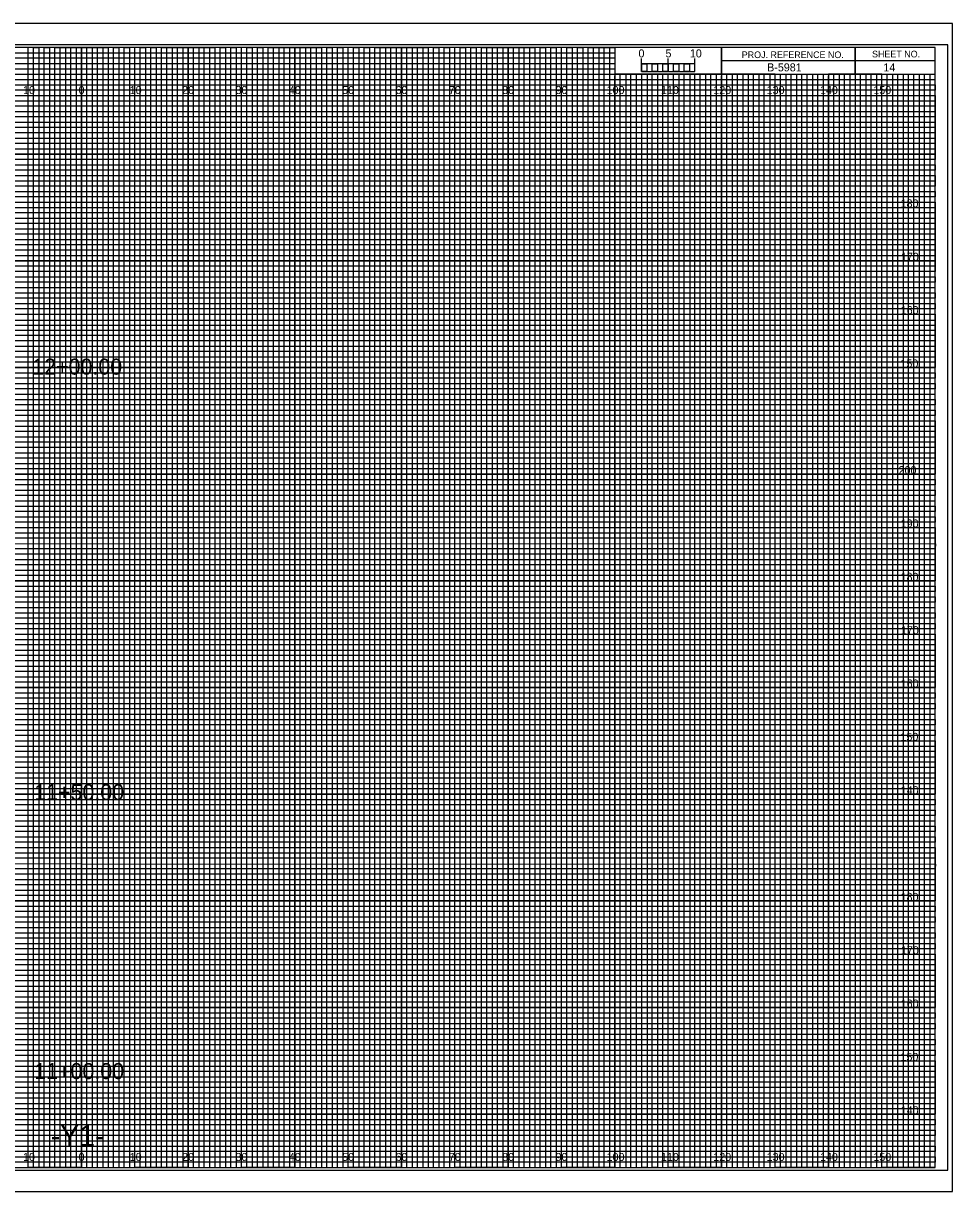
# Model space of a CAD drawing. Extents: x -13 to 323, y -5 to 434.
# Drawn here: x 149.1 to 323.3, y -4.5 to 214.5 of the extents above; entities that cross this region are included whole.
import ezdxf

# ---------------------------------------------------------------- set-up
doc = ezdxf.new("R2010")
doc.units = 0
for name, color, linetype in [('Exist Cross Section Cell', 7, 'Continuous'), ('Exist XS Center Line Elevation Label', 7, 'Continuous'), ('Exist XS Ground Line', 7, 'Continuous'), ('Prop CMT Concrete Structures', 7, 'Continuous'), ('Prop CMT Guardrail Graphics', 7, 'Continuous'), ('Prop CMT Pvmt Course 1', 7, 'Continuous'), ('Prop CMT Pvmt Course 2', 7, 'Continuous'), ('Prop CMT Pvmt Course 3', 7, 'Continuous'), ('Prop CMT Pvmt Surface', 7, 'Continuous'), ('Prop CMT Shld Paved Course 1', 7, 'Continuous'), ('Prop CMT Shld Paved Course 2', 7, 'Continuous'), ('Prop CMT Shld Paved Course 3', 7, 'Continuous'), ('Prop CMT Subgrade Earthwork', 7, 'Continuous'), ('Prop XS Ditch Standard Text', 7, 'Continuous'), ('Prop XS SE Text', 7, 'Continuous'), ('Prop XS Side Slope Text', 7, 'Continuous'), ('Scratch_Level_0', 7, 'Continuous')]:
    doc.layers.add(name, color=color, linetype=linetype)

msp = doc.modelspace()

# ---------------------------------------------------------------- linework, layer by layer
at = {"layer": 'Exist XS Center Line Elevation Label'}
for points in [[(145, 0), (155, 0), (155, 210), (165, 210), (165, 0), (175, 0), (175, 210), (185, 210), (185, 0), (195, 0), (195, 210), (205, 210), (205, 0), (215, 0), (215, 210), (225, 210), (225, 0), (235, 0), (235, 210), (245, 210), (245, 0), (255, 0), (255, 210), (259.93, 210), (260, 210), (260, 205), (264.99, 205), (264.99, 0), (275, 0), (275, 205), (285, 205), (285, 0), (295, 0), (295, 205), (305, 205), (305, 0), (315, 0), (315, 205)], [(0, 205), (275, 205)], [(0, 185), (320, 185), (320, 195), (0, 195)], [(0, 165), (320, 165), (320, 175), (0, 175)], [(0, 145), (320, 145), (320, 155), (0, 155)], [(0, 125), (320, 125), (320, 135), (0, 135)], [(0, 105), (320, 105), (320, 115), (0, 115)], [(0, 85), (320, 85), (320, 95), (0, 95)], [(0, 65), (320, 65), (320, 75), (0, 75)], [(0, 45), (320, 45), (320, 55), (0, 55)], [(0, 25), (320, 25), (320, 35), (0, 35)], [(0, 5), (320, 5), (320, 15), (0, 15)]]:
    msp.add_lwpolyline(points, dxfattribs=at)
at = {"layer": 'Exist XS Ground Line'}
for p, q in [((150, 210), (140, 210)), ((150, 0), (150, 210)), ((170, 210), (160, 210)), ((160, 210), (160, 0)), ((170, 0), (170, 210)), ((190, 210), (180, 210)), ((180, 210), (180, 0)), ((190, 0), (190, 210)), ((210, 210), (200, 210)), ((200, 210), (200, 0)), ((210, 0), (210, 210)), ((230, 210), (220, 210)), ((220, 210), (220, 0)), ((230, 0), (230, 210)), ((250, 210), (240, 210)), ((240, 210), (240, 0)), ((250, 0), (250, 210)), ((260, 210), (260, 0)), ((270, 0), (270, 205)), ((290, 205), (280, 205)), ((280, 205), (280, 0)), ((290, 0), (290, 205)), ((310, 205), (300, 205)), ((300, 205), (300, 0)), ((310, 0), (310, 205)), ((160, 0), (150, 0)), ((180, 0), (170, 0)), ((200, 0), (190, 0)), ((220, 0), (210, 0)), ((240, 0), (230, 0)), ((260, 0), (250, 0)), ((280, 0), (270, 0)), ((300, 0), (290, 0)), ((320, 0), (310, 0)), ((320, 0), (320, 0))]:
    msp.add_line(p, q, dxfattribs=at)
for points in [[(0, 200), (320, 200), (320, 190), (0, 190)], [(0, 180), (320, 180), (320, 170), (0, 170)], [(0, 160), (320, 160), (320, 150), (0, 150)], [(0, 140), (320, 140), (320, 130), (0, 130)], [(0, 120), (320, 120), (320, 110), (0, 110)], [(0, 100), (320, 100), (320, 90), (0, 90)], [(0, 80), (320, 80), (320, 70), (0, 70)], [(0, 60), (320, 60), (320, 50), (0, 50)], [(0, 40), (320, 40), (320, 30), (0, 30)], [(0, 20), (320, 20), (320, 10), (0, 10)]]:
    msp.add_lwpolyline(points, dxfattribs=at)
at = {"layer": 'Prop CMT Pvmt Course 1'}
for p, q in [((323.3, 214.5), (-13.4, 214.5)), ((-13.4, -4.5), (323.3, -4.5))]:
    msp.add_line(p, q, dxfattribs=at)
at = {"layer": 'Prop CMT Pvmt Course 2'}
msp.add_lwpolyline([(-13.4, -4.5), (323.3, -4.5), (323.3, 214.5), (-13.4, 214.5)], close=True, dxfattribs=at)
at = {"layer": 'Prop CMT Pvmt Course 3'}
msp.add_lwpolyline([(-10.8, -0.5), (322.4, -0.5), (322.4, 210.5), (-10.8, 210.5)], close=True, dxfattribs=at)
at = {"layer": 'Prop CMT Shld Paved Course 1'}
for p, q in [((305, 210), (305, 205)), ((305, 205), (305, 210)), ((280, 207.5), (280, 205)), ((320, 207.49), (280, 207.49)), ((280, 205), (320, 205))]:
    msp.add_line(p, q, dxfattribs=at)
for points in [[(320, 210), (0, 210), (0, 0), (320, 0)], [(280, 210), (260, 210), (260, 205.03), (280, 205.03)], [(320, 210), (280, 210), (280, 205), (320, 205)]]:
    msp.add_lwpolyline(points, close=True, dxfattribs=at)
at = {"layer": 'Prop CMT Shld Paved Course 2'}
for p, q in [((267, 205), (266.01, 205)), ((266.01, 205), (266.01, 0)), ((267, 0), (267, 205)), ((269, 205), (268, 205)), ((268, 205), (268, 0)), ((269, 0), (269, 205)), ((266.01, 0), (265, 0)), ((268, 0), (267, 0))]:
    msp.add_line(p, q, dxfattribs=at)
for points in [[(150, 0), (151, 0), (151, 210), (152, 210), (152, 0)], [(152, 0), (153, 0), (153, 210), (154, 210), (154, 0)], [(155, 0), (156, 0), (156, 210), (157, 210), (157, 0)], [(157, 0), (158, 0), (158, 210), (159, 210), (159, 0)], [(160, 0), (161, 0), (161, 210), (162, 210), (162, 0)], [(162, 0), (163, 0), (163, 210), (164, 210), (164, 0)], [(165, 0), (166, 0), (166, 210), (167, 210), (167, 0)], [(167, 0), (168, 0), (168, 210), (169, 210), (169, 0)], [(170, 0), (171, 0), (171, 210), (172, 210), (172, 0)], [(172, 0), (173, 0), (173, 210), (174, 210), (174, 0)], [(175, 0), (176, 0), (176, 210), (177, 210), (177, 0)], [(177, 0), (178, 0), (178, 210), (179, 210), (179, 0)], [(180, 0), (181, 0), (181, 210), (182, 210), (182, 0)], [(182, 0), (183, 0), (183, 210), (184, 210), (184, 0)], [(185, 0), (186, 0), (186, 210), (187, 210), (187, 0)], [(187, 0), (188, 0), (188, 210), (189, 210), (189, 0)], [(190, 0), (191, 0), (191, 210), (192, 210), (192, 0)], [(192, 0), (193, 0), (193, 210), (194, 210), (194, 0)], [(195, 0), (196, 0), (196, 210), (197, 210), (197, 0)], [(197, 0), (198, 0), (198, 210), (199, 210), (199, 0)], [(200, 0), (201, 0), (201, 210), (202, 210), (202, 0)], [(202, 0), (203, 0), (203, 210), (204, 210), (204, 0)], [(205, 0), (206, 0), (206, 210), (207, 210), (207, 0)], [(207, 0), (208, 0), (208, 210), (209, 210), (209, 0)], [(210, 0), (211, 0), (211, 210), (212, 210), (212, 0)], [(212, 0), (213, 0), (213, 210), (214, 210), (214, 0)], [(215, 0), (216, 0), (216, 210), (217, 210), (217, 0)], [(217, 0), (218, 0), (218, 210), (219, 210), (219, 0)], [(220, 0), (221, 0), (221, 210), (222, 210), (222, 0)], [(222, 0), (223, 0), (223, 210), (224, 210), (224, 0)], [(225, 0), (226, 0), (226, 210), (227, 210), (227, 0)], [(227, 0), (228, 0), (228, 210), (229, 210), (229, 0)], [(230, 0), (231, 0), (231, 210), (232, 210), (232, 0)], [(232, 0), (233, 0), (233, 210), (234, 210), (234, 0)], [(235, 0), (236, 0), (236, 210), (237, 210), (237, 0)], [(237, 0), (238, 0), (238, 210), (239, 210), (239, 0)], [(240, 0), (241, 0), (241, 210), (242, 210), (242, 0)], [(242, 0), (243, 0), (243, 210), (244, 210), (244, 0)], [(245, 0), (246, 0), (246, 210), (247, 210), (247, 0)], [(247, 0), (248, 0), (248, 210), (249, 210), (249, 0)], [(250, 0), (251, 0), (251, 210), (252, 210), (252, 0)], [(252, 0), (253, 0), (253, 210), (254, 210), (254, 0)], [(255, 0), (256, 0), (256, 210), (257, 210), (257, 0)], [(257, 0), (258, 0), (258, 210), (259, 210), (259, 0)], [(260, 0), (261, 0), (261, 205), (262.02, 205), (262.02, 0)], [(262, 0), (263, 0), (263, 205), (263.99, 205), (263.99, 0)], [(270, 0), (270.98, 0), (270.98, 205), (272, 205), (272, 0)], [(272, 0), (273, 0), (273, 205), (274.05, 205), (274.05, 0)], [(275, 0), (276, 0), (276, 205), (277, 205), (277, 0)], [(277, 0), (278, 0), (278, 205), (279, 205), (279, 0)], [(280, 0), (281, 0), (281, 205), (282, 205), (282, 0)], [(282, 0), (283, 0), (283, 205), (284, 205), (284, 0)], [(285, 0), (286, 0), (286, 205), (287, 205), (287, 0)], [(287, 0), (288, 0), (288, 205), (289, 205), (289, 0)], [(290, 0), (291, 0), (291, 205), (292, 205), (292, 0)], [(292, 0), (293, 0), (293, 205), (294, 205), (294, 0)], [(295, 0), (296, 0), (296, 205), (297, 205), (297, 0)], [(297, 0), (298, 0), (298, 205), (299, 205), (299, 0)], [(300, 0), (301, 0), (301, 205), (302, 205), (302, 0)], [(302, 0), (303, 0), (303, 205), (304, 205), (304, 0)], [(305, 0), (306, 0), (306, 205), (307, 205), (307, 0)], [(307, 0), (308, 0), (308, 205), (309, 205), (309, 0)], [(310, 0), (311, 0), (311, 205), (312, 205), (312, 0)], [(312, 0), (313, 0), (313, 205), (314, 205), (314, 0)], [(315, 0), (316, 0), (316, 205), (317, 205), (317, 0)], [(317, 0), (318, 0), (318, 205), (319, 205), (319, 0)]]:
    msp.add_lwpolyline(points, dxfattribs=at)
at = {"layer": 'Prop CMT Shld Paved Course 3'}
for p, q in [((265, 205.49), (265, 207.9)), ((265, 206.9), (265, 207.9)), ((270, 205.49), (270, 207.9)), ((275, 205.49), (275, 207.9)), ((275, 206.9), (275, 207.9))]:
    msp.add_line(p, q, dxfattribs=at)
for points in [[(275, 206.9), (265, 206.9), (265, 205.49), (275, 205.49)], [(265, 206.9), (266, 206.9), (266, 205.49), (265, 205.49)], [(267, 206.9), (268, 206.9), (268, 205.49), (267, 205.49)], [(269, 206.9), (270, 206.9), (270, 205.49), (269, 205.49)], [(271, 206.9), (272, 206.9), (272, 205.49), (271, 205.49)], [(273, 206.9), (274, 206.9), (274, 205.49), (273, 205.49)]]:
    msp.add_lwpolyline(points, close=True, dxfattribs=at)
at = {"layer": 'Prop CMT Subgrade Earthwork'}
for p, q in [((150, 0), (150, 210)), ((160, 0), (160, 210)), ((170, 0), (170, 210)), ((180, 0), (180, 210)), ((190, 0), (190, 210)), ((200, 0), (200, 210)), ((210, 0), (210, 210)), ((220, 0), (220, 210)), ((230, 0), (230, 210)), ((240, 0), (240, 210)), ((250, 0), (250, 210)), ((260, 0), (260, 204.69)), ((270, 0), (270, 204.69)), ((280, 0), (280, 204.69)), ((290, 0), (290, 204.69)), ((300, 0), (300, 204.69)), ((310, 0), (310, 204.69)), ((0, 200), (320, 200)), ((0, 190), (320, 190)), ((0, 180), (320, 180)), ((0, 170), (320, 170)), ((0, 160), (320, 160)), ((0, 150), (320, 150)), ((0, 140), (320, 140)), ((0, 130), (320, 130)), ((0, 120), (320, 120)), ((0, 110), (320, 110)), ((0, 100), (320, 100)), ((0, 90), (320, 90)), ((0, 80), (320, 80)), ((0, 70), (320, 70)), ((0, 60), (320, 60)), ((0, 50), (320, 50)), ((0, 40), (320, 40)), ((0, 30), (320, 30)), ((0, 20), (320, 20)), ((0, 10), (320, 10))]:
    msp.add_line(p, q, dxfattribs=at)
at = {"layer": 'Scratch_Level_0'}
for p, q in [((0, 209), (260, 209)), ((260, 209), (260, 207.98)), ((260, 207.98), (0, 207.98)), ((0, 207), (260, 207)), ((260, 205.89), (0, 205.89)), ((260, 207), (260, 205.89)), ((0, 204), (320, 204))]:
    msp.add_line(p, q, dxfattribs=at)
for points in [[(0, 203), (270, 203), (320, 203), (320, 202), (0, 202)], [(0, 201), (320, 201), (320, 199), (0, 199)], [(0, 198), (320, 198), (320, 197), (0, 196.98)], [(0, 196), (320, 196), (320, 194), (0, 194)], [(0, 193), (320, 193), (320, 192), (0, 192)], [(0, 191), (320, 191), (320, 189), (0, 189)], [(0, 188), (320, 188), (320, 187), (0, 187)], [(0, 186), (320, 186), (320, 184), (0, 184)], [(0, 183), (320, 183), (320, 182), (0, 182)], [(0, 181), (320, 181), (320, 179), (0, 179)], [(0, 178), (320, 178), (320, 177), (0, 177)], [(0, 176), (320, 176), (320, 173.95), (320, 173), (320, 172), (0, 172)], [(0, 174), (320, 174), (320, 173), (0, 173)], [(0, 171), (320, 171), (320, 169), (0, 169.03)], [(0, 169.03), (320, 169), (320, 168), (0, 168)], [(0, 167), (320, 167), (320, 166), (0, 166)], [(0, 164), (320, 164), (320, 163), (0, 163)], [(0, 162), (320, 162), (320, 161), (0, 161)], [(-0.07, 158.89), (320, 158.89), (320, 157.88), (-0.07, 157.88)], [(0, 157), (320, 157), (320, 156), (0, 156)], [(0, 154), (320, 154), (320, 153), (0, 153)], [(0, 152), (320, 152), (320, 151), (0, 151)], [(0, 149), (320, 149), (320, 148), (0, 148)], [(0, 147), (320, 147), (320, 146), (0, 146)], [(0, 144), (320, 144), (320, 143), (0, 143)], [(0, 142), (320, 142), (320, 141), (0, 141)], [(0, 139), (320, 139), (319.99, 137.98), (0, 138)], [(0, 137), (320, 137), (320, 136), (0, 136)], [(0, 134), (320, 134), (320, 133), (0, 133)], [(0, 132), (320, 132), (320, 131), (0, 131)], [(0, 129), (320, 129), (320, 128), (0, 128)], [(0, 127), (320, 127), (320, 126), (0, 126)], [(0, 124), (320, 124), (320, 123), (0, 123)], [(0, 122), (320, 122), (320, 121), (0, 121)], [(0, 119), (320, 119), (320, 118), (0, 118)], [(0, 116.99), (320.07, 116.91), (320, 116), (0, 116)], [(0, 114), (320, 114), (320, 113), (0, 113)], [(0, 112), (320, 112), (320, 111), (0, 111)], [(0, 109), (320, 109), (320, 108), (0, 108)], [(0, 107), (320, 107), (320, 106), (0, 106)], [(0, 104), (320, 104), (320, 103), (0, 103)], [(0, 102), (320, 102), (320, 101), (0, 101)], [(0, 99), (320, 99), (320, 98), (0, 98)], [(0, 97), (320, 97), (320, 96), (0, 96)], [(0, 94), (320, 94), (320, 93), (0, 93)], [(0, 92), (320, 92), (320, 91), (0, 91)], [(0, 89), (320, 89), (320, 88), (0, 88)], [(0, 87), (320, 87), (320, 86), (0, 86)], [(0, 84), (320, 84), (320, 83), (0, 83)], [(0, 82), (320, 82), (320, 81), (0, 81)], [(0, 79), (320, 79), (319.99, 77.98), (0, 78)], [(0, 77), (320, 77), (320, 76), (0, 76)], [(0, 74), (320, 74), (320, 73), (0, 73)], [(0, 72), (320, 72), (320, 71), (0, 71)], [(0, 69), (320, 69), (320, 68), (0, 68)], [(0, 67), (320, 67), (320, 66), (0, 66)], [(0, 64), (320, 64), (320, 63), (0, 63)], [(0, 62), (320, 62), (320, 61), (0, 61)], [(0, 59), (320, 59), (320, 58), (0, 58)], [(0, 56.99), (320.07, 56.91), (320, 56), (0, 56)], [(0, 54), (320, 54), (320, 53), (0, 53)], [(0, 52), (320, 52), (320, 51), (0, 51)], [(0, 49), (320, 49), (320, 48), (0, 48)], [(0, 47), (320, 47), (320, 46), (0, 46)], [(0, 44), (320, 44), (320, 43), (0, 43)], [(0, 42), (320, 42), (320, 41), (0, 41)], [(0, 39), (320, 39), (320, 38), (0, 38)], [(0, 37), (320, 37), (320, 36), (0, 36)], [(0, 34), (320, 34), (320, 33), (0, 33)], [(0, 32), (320, 32), (320, 31), (0, 31)], [(0, 29), (320, 29), (320, 28), (0, 28)], [(0, 27), (320, 27), (320, 26), (0, 26)], [(0, 24), (320, 24), (320, 23), (0, 23)], [(0, 22), (320, 22), (320, 21), (0, 21)], [(0, 19), (320, 19), (320, 18), (0, 18)], [(0, 17), (320, 17), (320, 16), (0, 16)], [(0, 14), (320, 14), (320, 13), (0, 13)], [(0, 12), (320, 12), (320, 11), (0, 11)], [(0, 9), (320, 9), (320, 8), (0, 8)], [(0, 7), (320, 7), (320, 6), (0, 6)], [(0, 4), (320, 4), (320, 3), (0, 3)], [(0, 2), (320, 2), (320, 1), (0, 1)]]:
    msp.add_lwpolyline(points, dxfattribs=at)

# ---------------------------------------------------------------- texts
at = {"layer": 'Exist Cross Section Cell'}
for s, p in [('10', (149.04, 201.25)), ('0', (159.45, 201.25)), ('0', (159.45, 201.25)), ('10', (169.04, 201.25)), ('20', (178.86, 201.25)), ('30', (188.86, 201.25)), ('40', (198.86, 201.25)), ('50', (208.86, 201.25)), ('60', (218.86, 201.25)), ('70', (228.86, 201.25)), ('80', (238.86, 201.25)), ('90', (248.86, 201.25)), ('100', (258.44, 201.25)), ('110', (268.62, 201.25)), ('120', (278.44, 201.25)), ('130', (288.44, 201.25)), ('140', (298.44, 201.25)), ('150', (308.44, 201.25)), ('10', (149.04, 1.25)), ('0', (159.45, 1.25)), ('0', (159.45, 1.25)), ('10', (169.04, 1.25)), ('20', (178.86, 1.25)), ('30', (188.86, 1.25)), ('40', (198.86, 1.25)), ('50', (208.86, 1.25)), ('60', (218.86, 1.25)), ('70', (228.86, 1.25)), ('80', (238.86, 1.25)), ('90', (248.86, 1.25)), ('100', (258.44, 1.25)), ('110', (268.62, 1.25)), ('120', (278.44, 1.25)), ('130', (288.44, 1.25)), ('140', (298.44, 1.25)), ('150', (308.44, 1.25))]:
    msp.add_text(s, height=1.5, dxfattribs=at).set_placement(p)
at = {"layer": 'Prop CMT Concrete Structures'}
for s, p in [('12+00.00', (150.77, 148.65)), ('11+50.00', (151.13, 68.89)), ('11+00.00', (151.13, 16.6))]:
    msp.add_text(s, height=3, dxfattribs=at).set_placement(p)
at = {"layer": 'Prop CMT Guardrail Graphics'}
for s, p in [('180', (313.55, 180)), ('170', (313.61, 170)), ('160', (313.57, 160)), ('150', (313.52, 150)), ('200', (313.17, 130)), ('190', (313.57, 120)), ('180', (313.55, 110)), ('170', (313.61, 100)), ('160', (313.57, 90)), ('150', (313.52, 80)), ('140', (313.57, 70)), ('180', (313.55, 50)), ('170', (313.61, 40)), ('160', (313.57, 30)), ('150', (313.52, 20)), ('140', (313.57, 10))]:
    msp.add_text(s, height=1.5, dxfattribs=at).set_placement(p)
at = {"layer": 'Prop CMT Pvmt Surface'}
for s, p in [('5', (269.47, 208.12)), ('10', (274.04, 208.12))]:
    msp.add_text(s, height=1.5, dxfattribs=at).set_placement(p)
at = {"layer": 'Prop CMT Shld Paved Course 1'}
for s, p in [('PROJ. REFERENCE NO.', (283.77, 207.99)), ('SHEET NO.', (308.19, 208.12))]:
    msp.add_text(s, height=1.25, dxfattribs=at).set_placement(p)
at = {"layer": 'Prop CMT Shld Paved Course 3'}
msp.add_text('0', height=1.5, dxfattribs=at).set_placement((264.41, 208.12))
at = {"layer": 'Prop XS Ditch Standard Text'}
msp.add_text('-Y1-', height=4, dxfattribs=at).set_placement((154.21, 4))
at = {"layer": 'Prop XS SE Text'}
msp.add_text('B-5981', height=1.5, dxfattribs=at).set_placement((288.53, 205.5))
at = {"layer": 'Prop XS Side Slope Text'}
msp.add_text('14', height=1.5, dxfattribs=at).set_placement((310.32, 205.5))

doc.saveas('drawing.dxf')
